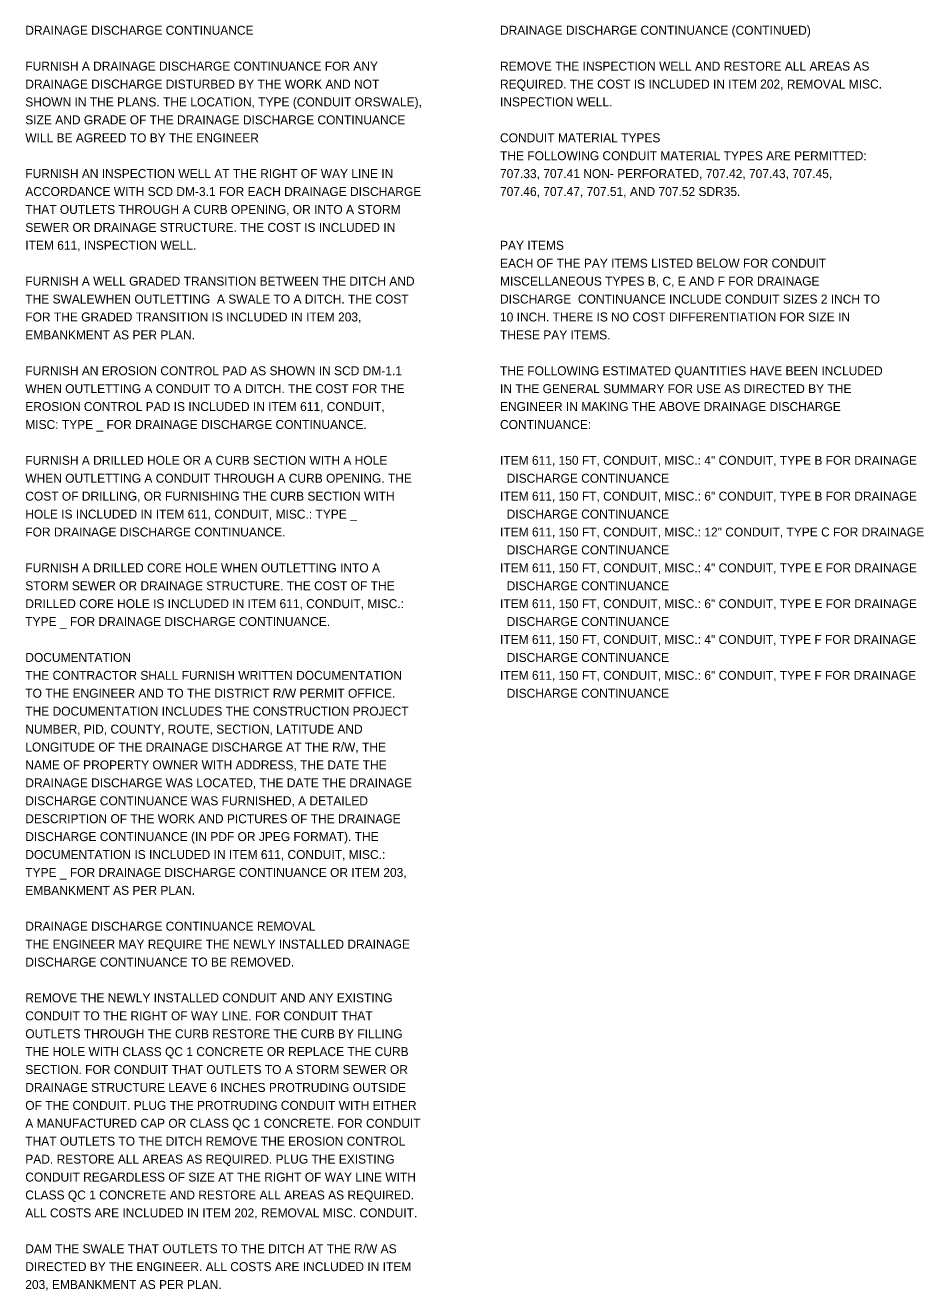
# Model space of a CAD drawing. Extents: x -14.4 to 34, y 0 to 22.
# Drawn here: x -14.45 to -0.41, y 1.56 to 21.34 of the extents above; entities that cross this region are included whole.
import ezdxf

# ---------------------------------------------------------------- set-up
doc = ezdxf.new("R2010")
doc.units = 0
doc.layers.add('SH_Text', color=7, linetype='Continuous')

msp = doc.modelspace()

# ---------------------------------------------------------------- texts
at = {"layer": 'SH_Text'}
for s, p in [('DRAINAGE DISCHARGE CONTINUANCE', (-14.45, 21.188)), ('DRAINAGE DISCHARGE CONTINUANCE (CONTINUED)', (-7.03, 21.188)), ('FURNISH A DRAINAGE DISCHARGE CONTINUANCE FOR ANY', (-14.45, 20.628)), ('REMOVE THE INSPECTION WELL AND RESTORE ALL AREAS AS', (-7.03, 20.628)), ('DRAINAGE DISCHARGE DISTURBED BY THE WORK AND NOT', (-14.45, 20.348)), ('REQUIRED. THE COST IS INCLUDED IN ITEM 202, REMOVAL MISC.', (-7.03, 20.348)), ('SHOWN IN THE PLANS. THE LOCATION, TYPE (CONDUIT ORSWALE),', (-14.45, 20.068)), ('INSPECTION WELL.', (-7.03, 20.068)), ('SIZE AND GRADE OF THE DRAINAGE DISCHARGE CONTINUANCE', (-14.45, 19.788)), ('WILL BE AGREED TO BY THE ENGINEER', (-14.45, 19.508)), ('CONDUIT MATERIAL TYPES', (-7.03, 19.508)), ('THE FOLLOWING CONDUIT MATERIAL TYPES ARE PERMITTED:', (-7.03, 19.228)), ('FURNISH AN INSPECTION WELL AT THE RIGHT OF WAY LINE IN', (-14.45, 18.948)), ('707.33, 707.41 NON- PERFORATED, 707.42, 707.43, 707.45,', (-7.03, 18.948)), ('ACCORDANCE WITH SCD DM-3.1 FOR EACH DRAINAGE DISCHARGE', (-14.45, 18.668)), ('707.46, 707.47, 707.51, AND 707.52 SDR35.', (-7.03, 18.668)), ('THAT OUTLETS THROUGH A CURB OPENING, OR INTO A STORM', (-14.45, 18.388)), ('SEWER OR DRAINAGE STRUCTURE. THE COST IS INCLUDED IN', (-14.45, 18.108)), ('ITEM 611, INSPECTION WELL.', (-14.45, 17.828)), ('PAY ITEMS', (-7.03, 17.828)), ('EACH OF THE PAY ITEMS LISTED BELOW FOR CONDUIT', (-7.03, 17.548)), ('FURNISH A WELL GRADED TRANSITION BETWEEN THE DITCH AND', (-14.45, 17.268)), ('MISCELLANEOUS TYPES B, C, E AND F FOR DRAINAGE', (-7.03, 17.268)), ('THE SWALEWHEN OUTLETTING  A SWALE TO A DITCH. THE COST', (-14.45, 16.988)), ('DISCHARGE  CONTINUANCE INCLUDE CONDUIT SIZES 2 INCH TO', (-7.03, 16.988)), ('FOR THE GRADED TRANSITION IS INCLUDED IN ITEM 203,', (-14.45, 16.708)), ('10 INCH. THERE IS NO COST DIFFERENTIATION FOR SIZE IN', (-7.03, 16.708)), ('EMBANKMENT AS PER PLAN.', (-14.45, 16.428)), ('THESE PAY ITEMS.', (-7.03, 16.428)), ('FURNISH AN EROSION CONTROL PAD AS SHOWN IN SCD DM-1.1', (-14.45, 15.868)), ('THE FOLLOWING ESTIMATED QUANTITIES HAVE BEEN INCLUDED', (-7.03, 15.868)), ('WHEN OUTLETTING A CONDUIT TO A DITCH. THE COST FOR THE', (-14.45, 15.588)), ('IN THE GENERAL SUMMARY FOR USE AS DIRECTED BY THE', (-7.03, 15.588)), ('EROSION CONTROL PAD IS INCLUDED IN ITEM 611, CONDUIT,', (-14.45, 15.308)), ('ENGINEER IN MAKING THE ABOVE DRAINAGE DISCHARGE', (-7.03, 15.308)), ('MISC: TYPE _ FOR DRAINAGE DISCHARGE CONTINUANCE.', (-14.45, 15.028)), ('CONTINUANCE:', (-7.03, 15.028)), ('FURNISH A DRILLED HOLE OR A CURB SECTION WITH A HOLE', (-14.45, 14.468)), ('ITEM 611, 150 FT, CONDUIT, MISC.: 4" CONDUIT, TYPE B FOR DRAINAGE', (-7.03, 14.468)), ('WHEN OUTLETTING A CONDUIT THROUGH A CURB OPENING. THE', (-14.45, 14.188)), ('  DISCHARGE CONTINUANCE', (-7.03, 14.188)), ('COST OF DRILLING, OR FURNISHING THE CURB SECTION WITH', (-14.45, 13.908)), ('ITEM 611, 150 FT, CONDUIT, MISC.: 6" CONDUIT, TYPE B FOR DRAINAGE', (-7.03, 13.908)), ('HOLE IS INCLUDED IN ITEM 611, CONDUIT, MISC.: TYPE _', (-14.45, 13.628)), ('  DISCHARGE CONTINUANCE', (-7.03, 13.628)), ('FOR DRAINAGE DISCHARGE CONTINUANCE.', (-14.45, 13.348)), ('ITEM 611, 150 FT, CONDUIT, MISC.: 12" CONDUIT, TYPE C FOR DRAINAGE', (-7.03, 13.348)), ('  DISCHARGE CONTINUANCE', (-7.03, 13.068)), ('FURNISH A DRILLED CORE HOLE WHEN OUTLETTING INTO A', (-14.45, 12.788)), ('ITEM 611, 150 FT, CONDUIT, MISC.: 4" CONDUIT, TYPE E FOR DRAINAGE', (-7.03, 12.788)), ('STORM SEWER OR DRAINAGE STRUCTURE. THE COST OF THE', (-14.45, 12.508)), ('  DISCHARGE CONTINUANCE', (-7.03, 12.508)), ('DRILLED CORE HOLE IS INCLUDED IN ITEM 611, CONDUIT, MISC.:', (-14.45, 12.228)), ('ITEM 611, 150 FT, CONDUIT, MISC.: 6" CONDUIT, TYPE E FOR DRAINAGE', (-7.03, 12.228)), ('TYPE _ FOR DRAINAGE DISCHARGE CONTINUANCE.', (-14.45, 11.948)), ('  DISCHARGE CONTINUANCE', (-7.03, 11.948)), ('ITEM 611, 150 FT, CONDUIT, MISC.: 4" CONDUIT, TYPE F FOR DRAINAGE', (-7.03, 11.668)), ('DOCUMENTATION', (-14.45, 11.388)), ('  DISCHARGE CONTINUANCE', (-7.03, 11.388)), ('THE CONTRACTOR SHALL FURNISH WRITTEN DOCUMENTATION', (-14.45, 11.108)), ('ITEM 611, 150 FT, CONDUIT, MISC.: 6" CONDUIT, TYPE F FOR DRAINAGE', (-7.03, 11.108)), ('TO THE ENGINEER AND TO THE DISTRICT R/W PERMIT OFFICE.', (-14.45, 10.828)), ('  DISCHARGE CONTINUANCE', (-7.03, 10.828)), ('THE DOCUMENTATION INCLUDES THE CONSTRUCTION PROJECT', (-14.45, 10.548)), ('NUMBER, PID, COUNTY, ROUTE, SECTION, LATITUDE AND', (-14.45, 10.268)), ('LONGITUDE OF THE DRAINAGE DISCHARGE AT THE R/W, THE', (-14.45, 9.988)), ('NAME OF PROPERTY OWNER WITH ADDRESS, THE DATE THE', (-14.45, 9.708)), ('DRAINAGE DISCHARGE WAS LOCATED, THE DATE THE DRAINAGE', (-14.45, 9.428)), ('DISCHARGE CONTINUANCE WAS FURNISHED, A DETAILED', (-14.45, 9.148)), ('DESCRIPTION OF THE WORK AND PICTURES OF THE DRAINAGE', (-14.45, 8.868)), ('DISCHARGE CONTINUANCE (IN PDF OR JPEG FORMAT). THE', (-14.45, 8.588)), ('DOCUMENTATION IS INCLUDED IN ITEM 611, CONDUIT, MISC.:', (-14.45, 8.308)), ('TYPE _ FOR DRAINAGE DISCHARGE CONTINUANCE OR ITEM 203,', (-14.45, 8.028)), ('EMBANKMENT AS PER PLAN.', (-14.45, 7.748)), ('DRAINAGE DISCHARGE CONTINUANCE REMOVAL', (-14.45, 7.188)), ('THE ENGINEER MAY REQUIRE THE NEWLY INSTALLED DRAINAGE', (-14.45, 6.908)), ('DISCHARGE CONTINUANCE TO BE REMOVED.', (-14.45, 6.628)), ('REMOVE THE NEWLY INSTALLED CONDUIT AND ANY EXISTING', (-14.45, 6.068)), ('CONDUIT TO THE RIGHT OF WAY LINE. FOR CONDUIT THAT', (-14.45, 5.788)), ('OUTLETS THROUGH THE CURB RESTORE THE CURB BY FILLING', (-14.45, 5.508)), ('THE HOLE WITH CLASS QC 1 CONCRETE OR REPLACE THE CURB', (-14.45, 5.228)), ('SECTION. FOR CONDUIT THAT OUTLETS TO A STORM SEWER OR', (-14.45, 4.948)), ('DRAINAGE STRUCTURE LEAVE 6 INCHES PROTRUDING OUTSIDE', (-14.45, 4.668)), ('OF THE CONDUIT. PLUG THE PROTRUDING CONDUIT WITH EITHER', (-14.45, 4.388)), ('A MANUFACTURED CAP OR CLASS QC 1 CONCRETE. FOR CONDUIT', (-14.45, 4.108)), ('THAT OUTLETS TO THE DITCH REMOVE THE EROSION CONTROL', (-14.45, 3.828)), ('PAD. RESTORE ALL AREAS AS REQUIRED. PLUG THE EXISTING', (-14.45, 3.548)), ('CONDUIT REGARDLESS OF SIZE AT THE RIGHT OF WAY LINE WITH', (-14.45, 3.268)), ('CLASS QC 1 CONCRETE AND RESTORE ALL AREAS AS REQUIRED.', (-14.45, 2.988)), ('ALL COSTS ARE INCLUDED IN ITEM 202, REMOVAL MISC. CONDUIT.', (-14.45, 2.708)), ('DAM THE SWALE THAT OUTLETS TO THE DITCH AT THE R/W AS', (-14.45, 2.148)), ('DIRECTED BY THE ENGINEER. ALL COSTS ARE INCLUDED IN ITEM', (-14.45, 1.868)), ('203, EMBANKMENT AS PER PLAN.', (-14.45, 1.588))]:
    msp.add_text(s, height=0.14, dxfattribs=at).set_placement(p)

doc.saveas('drawing.dxf')
